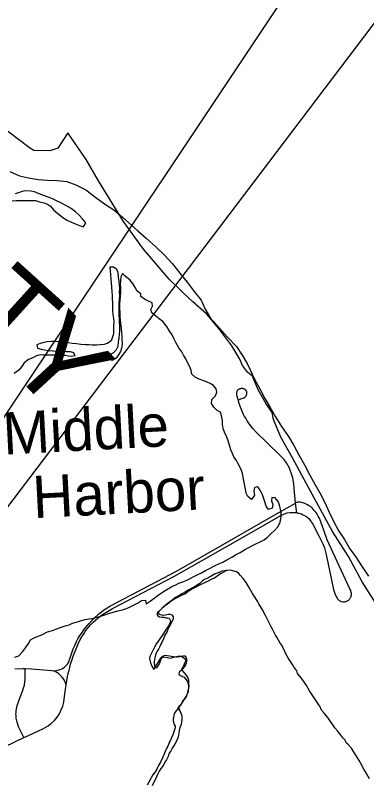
# Model space of a CAD drawing. Extents: x -12 to 34, y 0 to 22.
# Drawn here: x 3.469 to 4.257, y 18.646 to 20.374 of the extents above; entities that cross this region are included whole.
import ezdxf

# ---------------------------------------------------------------- set-up
doc = ezdxf.new("R2010")
doc.units = 0
for name, color, linetype in [('GM_X_Adjacent_County', 7, 'Continuous'), ('GM_X_Airport_Location_Class_2', 7, 'Continuous'), ('GM_X_Major_Lake_Text', 7, 'Continuous'), ('GM_X_Major_River', 7, 'Continuous'), ('GM_X_Minor_Lake', 7, 'Continuous'), ('GM_X_Minor_River', 7, 'Continuous'), ('GM_X_Minor_River_Text', 7, 'Continuous')]:
    doc.layers.add(name, color=color, linetype=linetype)

msp = doc.modelspace()

# ---------------------------------------------------------------- linework, layer by layer
at = {"layer": 'GM_X_Adjacent_County'}
msp.add_lwpolyline([(4.3077, 20.7695), (2.2584, 17.6954), (4.3077, 20.4)], close=True, dxfattribs=at)
at = {"layer": 'GM_X_Airport_Location_Class_2'}
msp.add_lwpolyline([(4.2894, 19.0359), (4.2477, 19.1014), (4.2165, 19.1581), (4.1808, 19.2148), (4.1493, 19.2726), (4.1226, 19.322), (4.0908, 19.38), (4.0645, 19.4267), (4.0481, 19.466), (4.0454, 19.4824), (4.032, 19.5012), (4.0137, 19.5331), (4.0011, 19.5638), (3.9901, 19.5729), (3.9785, 19.5879), (3.9729, 19.6019), (3.9546, 19.6317), (3.9254, 19.6709), (3.899, 19.7032), (3.8673, 19.7311), (3.8453, 19.751), (3.8144, 19.7819), (3.7561, 19.8493), (3.7118, 19.9114), (3.6551, 20.0027), (3.628, 20.0508), (3.5867, 20.1107), (3.5637, 20.0758), (3.5463, 20.0702), (3.5098, 20.0709), (3.5002, 20.0768), (3.4285, 20.1304)], dxfattribs=at)
msp.add_lwpolyline([(4.2894, 19.0359), (4.2477, 19.1014), (4.2165, 19.1581), (4.1808, 19.2148), (4.1493, 19.2726), (4.1226, 19.322), (4.0908, 19.38), (4.0645, 19.4267), (4.0481, 19.466), (4.0454, 19.4824), (4.032, 19.5012), (4.0137, 19.5331), (4.0011, 19.5638), (3.9901, 19.5729), (3.9785, 19.5879), (3.9729, 19.6019), (3.9546, 19.6317), (3.9254, 19.6709), (3.899, 19.7032), (3.8673, 19.7311), (3.8453, 19.751), (3.8144, 19.7819), (3.7561, 19.8493), (3.7118, 19.9114), (3.6551, 20.0027), (3.628, 20.0508), (3.5867, 20.1107), (3.5637, 20.0758), (3.5463, 20.0702), (3.5098, 20.0709), (3.5002, 20.0768), (3.4285, 20.1304)], dxfattribs=at)
at = {"layer": 'GM_X_Major_River'}
msp.add_line((4.1007, 19.2569), (4.098, 19.2786), dxfattribs=at)
for points in [[(3.9703, 19.5105), (3.9711, 19.511), (3.9719, 19.5113), (3.9735, 19.5119), (3.9752, 19.5124), (3.9794, 19.5139), (3.9805, 19.5143), (3.9814, 19.5148), (3.9822, 19.5152), (3.983, 19.5157), (3.984, 19.5164), (3.9847, 19.517), (3.9852, 19.5175), (3.9861, 19.5186), (3.9868, 19.5197), (3.9873, 19.5206), (3.9876, 19.5212), (3.9879, 19.5222), (3.9882, 19.5232), (3.9884, 19.5242), (3.9884, 19.5255), (3.9883, 19.5272), (3.9881, 19.5282), (3.9877, 19.5294), (3.9874, 19.5301), (3.9867, 19.5313), (3.9857, 19.5326), (3.9847, 19.5335), (3.984, 19.534), (3.9833, 19.5344), (3.9821, 19.535), (3.9805, 19.5355), (3.9789, 19.5358), (3.9774, 19.5359), (3.9759, 19.5358), (3.9744, 19.5356), (3.973, 19.5352), (3.9715, 19.5346), (3.9703, 19.5339), (3.9696, 19.5335), (3.969, 19.533), (3.9678, 19.5319), (3.9669, 19.5307), (3.9663, 19.5295), (3.9658, 19.528), (3.9655, 19.5265), (3.9653, 19.525), (3.9654, 19.5231), (3.9655, 19.5213), (3.9661, 19.5192), (3.9685, 19.5115)], [(4.098, 19.2786), (4.0966, 19.2948), (4.0951, 19.3113), (4.0937, 19.3225), (4.0928, 19.3296), (4.0917, 19.335), (4.0905, 19.3399), (4.0882, 19.3466), (4.0834, 19.3581), (4.0774, 19.3689), (4.072, 19.3764), (4.0659, 19.3835), (4.0324, 19.4157), (4.0099, 19.4369), (4.0016, 19.4462), (3.9942, 19.4561), (3.992, 19.4592), (3.9891, 19.4637), (3.9859, 19.4692), (3.9835, 19.4732), (3.9813, 19.4773), (3.9787, 19.4829), (3.974, 19.4944), (3.9706, 19.5045), (3.9699, 19.5069), (3.9696, 19.5079), (3.9696, 19.5086), (3.9697, 19.5093), (3.9703, 19.5105)], [(3.555, 18.9016), (3.5586, 18.9019), (3.5621, 18.9024), (3.564, 18.9028), (3.567, 18.9037), (3.5694, 18.9045), (3.5727, 18.906), (3.5767, 18.9083), (3.5792, 18.9101), (3.5807, 18.9112), (3.5829, 18.9132), (3.5845, 18.915), (3.5858, 18.9167), (3.5871, 18.9187), (3.5883, 18.921), (3.5893, 18.9233), (3.5903, 18.9259), (3.5962, 18.9443), (3.5988, 18.9511), (3.6019, 18.9588), (3.6035, 18.9621), (3.6059, 18.9672), (3.6093, 18.9734), (3.6137, 18.9806), (3.6193, 18.9888), (3.6242, 18.9961), (3.6288, 19.0018), (3.6341, 19.0081), (3.6448, 19.0194), (3.6564, 19.0298), (3.6688, 19.0391), (3.682, 19.0473), (3.8306, 19.1258), (3.8603, 19.1429), (3.9144, 19.1737), (4.0549, 19.254), (4.098, 19.2786)], [(4.2138, 19.0587), (4.2164, 19.0602), (4.218, 19.0614), (4.2192, 19.0627), (4.22, 19.0637), (4.2208, 19.0649), (4.2215, 19.0661), (4.2221, 19.0674), (4.2225, 19.0684), (4.2229, 19.0694), (4.2231, 19.0705), (4.2232, 19.0718), (4.2233, 19.0732), (4.2233, 19.0749), (4.2232, 19.076), (4.2231, 19.0768), (4.2228, 19.0785), (4.2223, 19.0799), (4.2219, 19.081), (4.221, 19.0834), (4.22, 19.0856), (4.2, 19.1279), (4.1691, 19.1957), (4.1625, 19.2131), (4.1576, 19.2279), (4.1564, 19.2321), (4.1548, 19.2367), (4.1531, 19.2406), (4.151, 19.2452), (4.1489, 19.2489), (4.1465, 19.2534), (4.1438, 19.2573), (4.1422, 19.2596), (4.1399, 19.2622), (4.1376, 19.2647), (4.135, 19.2675), (4.1337, 19.2685), (4.1321, 19.2699), (4.1299, 19.2716), (4.1273, 19.2733), (4.1249, 19.2748), (4.1219, 19.2762), (4.119, 19.2774), (4.1168, 19.2783), (4.1143, 19.2791), (4.1119, 19.2798), (4.1089, 19.2804), (4.1075, 19.2806), (4.1062, 19.2806), (4.1054, 19.2806), (4.1041, 19.2805), (4.1029, 19.2804), (4.1017, 19.28), (4.1003, 19.2795), (4.098, 19.2786)], [(3.5827, 18.87), (3.5833, 18.8744), (3.586, 18.889), (3.5866, 18.8921), (3.5873, 18.8957), (3.5892, 18.9033), (3.5907, 18.9094), (3.5928, 18.9168), (3.594, 18.9211), (3.5951, 18.9244), (3.5986, 18.9345), (3.6065, 18.9547), (3.6099, 18.9624), (3.6143, 18.9716), (3.6192, 18.9799), (3.623, 18.9857), (3.6255, 18.9896), (3.6294, 18.9951), (3.6346, 19.0015), (3.6384, 19.0059), (3.6433, 19.011), (3.6483, 19.0155), (3.6536, 19.0199), (3.6589, 19.0242), (3.6619, 19.0263), (3.6681, 19.0306), (3.687, 19.0413), (3.8246, 19.1133), (3.8866, 19.1487), (3.9945, 19.2103), (4.0645, 19.2506), (4.0729, 19.2546), (4.0788, 19.2565), (4.0849, 19.2574), (4.088, 19.2575), (4.0928, 19.2576), (4.0957, 19.2574), (4.0984, 19.2572), (4.1007, 19.2569)], [(4.1007, 19.2569), (4.1023, 19.2567), (4.1042, 19.2562), (4.1063, 19.2557), (4.1091, 19.2549), (4.111, 19.2542), (4.1136, 19.2531), (4.1178, 19.2509), (4.123, 19.2476), (4.1277, 19.2436), (4.1318, 19.2389), (4.1368, 19.231), (4.1512, 19.2035), (4.1593, 19.1868), (4.1627, 19.1781), (4.166, 19.1661), (4.1791, 19.1023), (4.1831, 19.0841), (4.1861, 19.0752), (4.1901, 19.0668), (4.1914, 19.0647), (4.1924, 19.0633), (4.1934, 19.0621), (4.1948, 19.0607), (4.1962, 19.0596), (4.1974, 19.0589), (4.1988, 19.0582), (4.2001, 19.0576), (4.2017, 19.0572), (4.2048, 19.0568), (4.2079, 19.0569), (4.2093, 19.0572), (4.2109, 19.0576), (4.2138, 19.0587)], [(3.4678, 18.9062), (3.4865, 18.907), (3.4903, 18.9069)], [(3.4874, 18.7515), (3.4767, 18.7743), (3.4735, 18.7831), (3.4724, 18.7866), (3.4718, 18.7893), (3.4713, 18.7923), (3.4707, 18.7954), (3.4703, 18.7978), (3.4701, 18.8015), (3.47, 18.8041), (3.4701, 18.8072), (3.4702, 18.8094), (3.4707, 18.8132), (3.471, 18.8154), (3.4719, 18.8201), (3.4729, 18.8233), (3.4741, 18.8272), (3.4755, 18.8321), (3.4853, 18.8578), (3.4871, 18.8633), (3.4879, 18.8659), (3.4889, 18.8695), (3.4895, 18.8724), (3.4899, 18.8748), (3.4901, 18.8778), (3.4903, 18.8811), (3.4905, 18.8845), (3.4903, 18.9069)], [(3.4903, 18.9069), (3.5051, 18.9064), (3.5497, 18.902), (3.555, 18.9016)], [(3.5827, 18.87), (3.5811, 18.8747), (3.5797, 18.8777), (3.5779, 18.881), (3.5743, 18.8864), (3.5722, 18.8885), (3.5676, 18.8934), (3.566, 18.8949), (3.5629, 18.8972), (3.555, 18.9016)], [(3.4874, 18.7515), (3.4978, 18.7565), (3.5317, 18.7721), (3.5425, 18.7782), (3.55, 18.7837), (3.5567, 18.7901), (3.5626, 18.7973), (3.5676, 18.8052), (3.5717, 18.8136), (3.575, 18.8223), (3.5773, 18.8313), (3.5799, 18.8497), (3.5827, 18.87)], [(3.2569, 18.6617), (3.2728, 18.6624), (3.2882, 18.6641), (3.3034, 18.6671), (3.3153, 18.6706), (3.3268, 18.6753), (3.3802, 18.7002), (3.4874, 18.7515)]]:
    msp.add_lwpolyline(points, dxfattribs=at)
at = {"layer": 'GM_X_Minor_Lake'}
for points in [[(3.4617, 19.9576), (3.4704, 19.9584), (3.4814, 19.9584), (3.4928, 19.9588), (3.5034, 19.9585), (3.5137, 19.9582), (3.5228, 19.9556), (3.5327, 19.9529), (3.5407, 19.9503), (3.5479, 19.9458), (3.5544, 19.9378), (3.5643, 19.9291), (3.5746, 19.9208), (3.5845, 19.9144), (3.5944, 19.9095), (3.6051, 19.9054), (3.6127, 19.9024), (3.6214, 19.899), (3.6271, 19.9081), (3.6191, 19.9176), (3.6118, 19.9255), (3.6034, 19.9331), (3.5939, 19.9407), (3.5817, 19.9475), (3.5706, 19.9535), (3.5596, 19.9584), (3.5505, 19.9629), (3.5425, 19.9659), (3.5315, 19.9697), (3.5223, 19.9734), (3.5113, 19.9779), (3.5033, 19.9794), (3.4912, 19.9801), (3.4836, 19.9786), (3.4756, 19.9759), (3.4684, 19.9736)], [(3.7501, 19.749), (3.7425, 19.755), (3.7372, 19.7641), (3.7314, 19.7725), (3.7257, 19.7804), (3.7162, 19.7876), (3.7089, 19.7944), (3.7055, 19.7868), (3.7044, 19.7777), (3.7041, 19.7693), (3.7045, 19.7621), (3.7046, 19.7533), (3.7039, 19.7419), (3.7031, 19.7339), (3.7024, 19.7267), (3.7025, 19.7157), (3.7033, 19.7062), (3.7033, 19.697), (3.7038, 19.6894), (3.7049, 19.6815), (3.7065, 19.6716), (3.7073, 19.6605), (3.7077, 19.6529), (3.7078, 19.645), (3.7082, 19.6377), (3.7079, 19.629), (3.7049, 19.6191), (3.7004, 19.6115), (3.6947, 19.6042), (3.686, 19.5992), (3.6784, 19.6045), (3.6802, 19.6117), (3.6897, 19.6167), (3.6961, 19.624), (3.6995, 19.6312), (3.7006, 19.64), (3.7017, 19.6499), (3.7028, 19.6575), (3.7035, 19.6662), (3.7034, 19.6761), (3.7026, 19.6845), (3.7022, 19.6917), (3.7014, 19.7008), (3.7014, 19.7084), (3.7017, 19.7198), (3.702, 19.7275), (3.7028, 19.7366), (3.7031, 19.7442), (3.7027, 19.7533), (3.703, 19.7609), (3.7022, 19.7681), (3.7014, 19.7769), (3.7006, 19.7868), (3.6994, 19.7963), (3.6963, 19.8035), (3.6887, 19.8084), (3.6811, 19.8084), (3.6812, 19.8004), (3.6823, 19.7916), (3.6828, 19.781), (3.684, 19.773), (3.6848, 19.7646), (3.6856, 19.7532), (3.6864, 19.746), (3.6864, 19.738), (3.6869, 19.7274), (3.6865, 19.7186), (3.6869, 19.711), (3.6874, 19.7023), (3.6893, 19.6932), (3.6897, 19.6859), (3.689, 19.6768), (3.6891, 19.6673), (3.6887, 19.6589), (3.6861, 19.6502), (3.6839, 19.6429), (3.6756, 19.6368), (3.6676, 19.6345), (3.6592, 19.6341), (3.6516, 19.6337), (3.6414, 19.6336), (3.6334, 19.634), (3.6262, 19.6339), (3.6156, 19.635), (3.6057, 19.6361), (3.5962, 19.6372)], [(3.7112, 19.7868), (3.7113, 19.7868)], [(3.9434, 19.1513), (3.9544, 19.1571), (3.9631, 19.1624), (3.9737, 19.1674), (3.9855, 19.1751), (3.9942, 19.1797), (4.0014, 19.1832), (4.0089, 19.1866), (4.0184, 19.1916), (4.0271, 19.1958), (4.0358, 19.2027), (4.0434, 19.21), (4.0509, 19.2168), (4.0585, 19.226), (4.063, 19.2355), (4.0645, 19.2428), (4.0652, 19.25), (4.0652, 19.2572), (4.064, 19.2652), (4.0617, 19.2736), (4.059, 19.2823), (4.0521, 19.2902), (4.0445, 19.2913), (4.0438, 19.2837), (4.0468, 19.275), (4.0457, 19.267), (4.037, 19.2639), (4.0321, 19.2715), (4.029, 19.281), (4.0263, 19.2882), (4.0236, 19.2973), (4.0186, 19.3076), (4.0132, 19.3148), (4.006, 19.3132), (4.0042, 19.3052), (4.0057, 19.2965), (3.9989, 19.2866), (3.9906, 19.2934), (3.9871, 19.301), (3.9855, 19.3097), (3.9836, 19.3169), (3.982, 19.3287), (3.9805, 19.3367), (3.9785, 19.345), (3.9754, 19.3541), (3.9693, 19.3667), (3.9651, 19.3739), (3.9593, 19.3822), (3.9563, 19.3898), (3.9528, 19.3985), (3.9493, 19.4084), (3.9466, 19.4187), (3.9432, 19.427), (3.9386, 19.438), (3.9355, 19.4464), (3.9339, 19.4551), (3.9335, 19.4631), (3.9323, 19.4715), (3.9292, 19.4828), (3.9216, 19.4862), (3.914, 19.4938), (3.9094, 19.5021), (3.9097, 19.5113), (3.9184, 19.5197), (3.9214, 19.5277), (3.9194, 19.5353), (3.9133, 19.5425), (3.9061, 19.5474), (3.8981, 19.5508), (3.8897, 19.5538), (3.8817, 19.5568), (3.8722, 19.5613), (3.8646, 19.5685), (3.8634, 19.5761), (3.8607, 19.5844), (3.8554, 19.5947), (3.8511, 19.6023), (3.8462, 19.611), (3.8423, 19.6182), (3.8354, 19.6277), (3.8289, 19.6394), (3.8243, 19.6485), (3.8209, 19.6569), (3.8144, 19.666), (3.8086, 19.6751), (3.7998, 19.6865), (3.7914, 19.6929), (3.7842, 19.6986), (3.775, 19.7061), (3.7731, 19.7137), (3.7765, 19.7213), (3.7757, 19.7286), (3.7677, 19.7323), (3.7589, 19.7365), (3.7502, 19.7429), (3.7501, 19.749)], [(3.5962, 19.6372), (3.5878, 19.6383), (3.578, 19.639), (3.5669, 19.6405), (3.5582, 19.6416), (3.5499, 19.6419), (3.5404, 19.6411), (3.5328, 19.6396), (3.5241, 19.6373), (3.5165, 19.6338), (3.5184, 19.6266), (3.5268, 19.6247), (3.5344, 19.6232), (3.542, 19.6217), (3.5526, 19.6203), (3.5629, 19.6199), (3.5739, 19.6196), (3.5826, 19.6193), (3.5917, 19.6189), (3.5993, 19.6167), (3.6024, 19.6091), (3.5952, 19.6079), (3.588, 19.609), (3.5808, 19.6098), (3.5736, 19.6101), (3.5663, 19.6108), (3.5572, 19.6112), (3.5496, 19.6108), (3.539, 19.6107), (3.5318, 19.6107), (3.5246, 19.6114), (3.5162, 19.6095), (3.5075, 19.6052), (3.498, 19.6014), (3.4886, 19.5934), (3.4829, 19.5857), (3.4762, 19.5769), (3.4663, 19.5697)], [(3.4673, 18.932), (3.4768, 18.9355), (3.4847, 18.9442), (3.4915, 18.9534), (3.4979, 18.9626), (3.5028, 18.9713), (3.5111, 18.9759), (3.5199, 18.9798), (3.5278, 18.9828), (3.5411, 18.989), (3.5521, 18.9921), (3.5615, 18.9963), (3.5718, 18.9994), (3.5805, 19.0025), (3.5892, 19.0048), (3.5968, 19.0083), (3.6101, 19.0121), (3.6173, 19.0148), (3.6252, 19.0168), (3.6347, 19.0183), (3.6419, 19.0195), (3.6491, 19.0211), (3.6578, 19.0234), (3.6692, 19.0272), (3.6775, 19.0307), (3.6912, 19.0342), (3.6991, 19.0361), (3.709, 19.0388), (3.7162, 19.0408), (3.7238, 19.0435), (3.7427, 19.0534), (3.7518, 19.0596), (3.7609, 19.06), (3.7621, 19.052), (3.7716, 19.0581), (3.7806, 19.065), (3.7897, 19.0719), (3.7969, 19.0765), (3.8048, 19.0822), (3.8124, 19.0868), (3.82, 19.0907), (3.8287, 19.0949), (3.8359, 19.0987), (3.8446, 19.1018), (3.8522, 19.1049), (3.8598, 19.1083), (3.8692, 19.1137), (3.8772, 19.1172), (3.8863, 19.1214), (3.8957, 19.1271), (3.9029, 19.131), (3.9177, 19.1379), (3.9268, 19.1425), (3.9344, 19.146), (3.9434, 19.1513)], [(3.9439, 19.1277), (3.9394, 19.1251), (3.9307, 19.1201), (3.9269, 19.1178), (3.922, 19.1143), (3.9156, 19.1101), (3.911, 19.1082), (3.9016, 19.1028), (3.8962, 19.1009), (3.8887, 19.0971), (3.8853, 19.0955), (3.8739, 19.0898), (3.8667, 19.0856), (3.8588, 19.081), (3.8489, 19.0741), (3.8451, 19.0725), (3.8395, 19.0698), (3.8326, 19.066), (3.8285, 19.0641), (3.8243, 19.0618), (3.8175, 19.0572), (3.8141, 19.0545), (3.8092, 19.0503), (3.8046, 19.0476), (3.8012, 19.0446), (3.7975, 19.0419), (3.7941, 19.0381), (3.791, 19.0346), (3.7892, 19.0308), (3.7926, 19.0286), (3.796, 19.0271), (3.8006, 19.0263), (3.8059, 19.0275), (3.812, 19.0287), (3.8165, 19.0291), (3.8203, 19.0272), (3.823, 19.0226), (3.823, 19.0181), (3.8211, 19.0135), (3.8174, 19.0055), (3.8132, 18.999), (3.8106, 18.9929), (3.8087, 18.9887), (3.8046, 18.9815), (3.8012, 18.9738), (3.7978, 18.9655), (3.7956, 18.9617), (3.793, 18.9563), (3.7903, 18.9506), (3.7873, 18.946), (3.7851, 18.9415), (3.7836, 18.9373), (3.7828, 18.9338), (3.7813, 18.9278), (3.7806, 18.9217), (3.7806, 18.9179), (3.7814, 18.9129), (3.7826, 18.9091), (3.786, 18.908), (3.7886, 18.9118), (3.792, 18.9175), (3.7939, 18.9217), (3.7954, 18.9259), (3.7965, 18.9297), (3.8003, 18.9332), (3.8098, 18.9313), (3.8132, 18.9306), (3.8166, 18.9302), (3.8216, 18.9317), (3.8269, 18.9333), (3.8333, 18.9345), (3.8367, 18.9349), (3.8413, 18.9345), (3.8474, 18.93), (3.8508, 18.9277), (3.8505, 18.9231), (3.8486, 18.9189), (3.8467, 18.914), (3.8448, 18.9098), (3.8418, 18.9056), (3.843, 18.9022), (3.8468, 18.898), (3.8506, 18.8935), (3.854, 18.8893), (3.856, 18.8855), (3.8575, 18.8813), (3.8575, 18.8756), (3.8576, 18.8722), (3.858, 18.8669), (3.8576, 18.8616), (3.8561, 18.8566), (3.8542, 18.8501), (3.8528, 18.8456), (3.8509, 18.8418), (3.8482, 18.8372), (3.8448, 18.8338), (3.8414, 18.8292), (3.8399, 18.8257), (3.8366, 18.8219), (3.8335, 18.8181), (3.8381, 18.8117)], [(4.2641, 18.6585), (4.2553, 18.6748), (4.2515, 18.6805), (4.2438, 18.6949), (4.2404, 18.6998), (4.2335, 18.7124), (4.2304, 18.7169), (4.2232, 18.7275), (4.2151, 18.737), (4.2113, 18.74), (4.2094, 18.7461), (4.2044, 18.751), (4.1976, 18.7597), (4.1918, 18.7665), (4.1861, 18.7737), (4.1804, 18.7821), (4.1762, 18.7874), (4.1704, 18.7965), (4.1624, 18.8063), (4.1563, 18.8135), (4.1521, 18.8219), (4.1498, 18.8253), (4.1444, 18.834), (4.1367, 18.8457), (4.1295, 18.8564), (4.1226, 18.8689), (4.1191, 18.873), (4.1115, 18.8852), (4.1019, 18.8958), (4.1004, 18.9015), (4.0943, 18.9102), (4.0912, 18.9159), (4.082, 18.9295), (4.0763, 18.9401), (4.0736, 18.9451), (4.0667, 18.9591), (4.0632, 18.964), (4.0556, 18.9769), (4.0525, 18.9815), (4.046, 18.9951), (4.0429, 19.0004), (4.0372, 19.0126), (4.0345, 19.0168), (4.0303, 19.0259), (4.0238, 19.0384), (4.0211, 19.0422), (4.0157, 19.0524), (4.013, 19.0566), (4.0073, 19.0661), (4.0015, 19.0752), (3.9924, 19.0911), (3.987, 19.1002), (3.9805, 19.1089), (3.974, 19.1161), (3.9702, 19.1206), (3.9652, 19.124), (3.9572, 19.1259), (3.9519, 19.1274), (3.939, 19.1266), (3.9326, 19.1254), (3.9261, 19.1227), (3.917, 19.1193), (3.9098, 19.115), (3.9011, 19.1101), (3.8932, 19.107), (3.889, 19.1035), (3.8826, 19.0978), (3.8735, 19.0921), (3.8648, 19.0875), (3.8569, 19.0825), (3.8485, 19.0779), (3.8428, 19.0744), (3.8383, 19.0717), (3.8281, 19.066), (3.8209, 19.0603), (3.8152, 19.0564), (3.8118, 19.0534), (3.8054, 19.048), (3.8016, 19.0453), (3.7963, 19.04), (3.7914, 19.0358), (3.7876, 19.0327), (3.7861, 19.0289), (3.7884, 19.0255), (3.7926, 19.0229), (3.7972, 19.0225), (3.8021, 19.0218), (3.8059, 19.021), (3.8105, 19.0207), (3.8139, 19.0199), (3.8166, 19.0157), (3.8173, 19.0123), (3.8159, 19.0085), (3.8144, 19.0051), (3.8113, 19.0001), (3.8061, 18.9929)], [(3.8061, 18.9929), (3.8015, 18.9856), (3.7966, 18.9788), (3.7932, 18.9738), (3.7891, 18.9681), (3.7857, 18.9628), (3.7812, 18.9551), (3.7771, 18.9475), (3.7725, 18.9384), (3.7707, 18.9338), (3.7699, 18.9292), (3.7703, 18.9254), (3.7719, 18.9193), (3.7757, 18.9106), (3.7796, 18.9049), (3.7833, 18.9103), (3.7852, 18.9137), (3.7878, 18.9183), (3.7905, 18.9225), (3.7942, 18.9293), (3.7984, 18.9339), (3.8026, 18.9362), (3.806, 18.9366), (3.8098, 18.9359), (3.8151, 18.9355), (3.8196, 18.9348), (3.8238, 18.9337), (3.828, 18.9329), (3.8318, 18.9329), (3.8383, 18.9341), (3.8417, 18.9345), (3.8458, 18.9353), (3.8493, 18.9349), (3.8519, 18.9307), (3.8527, 18.9269), (3.8531, 18.9231), (3.8524, 18.919), (3.8505, 18.9148), (3.8486, 18.9113), (3.8448, 18.9071), (3.8414, 18.9033), (3.8365, 18.8987), (3.8354, 18.8942), (3.8392, 18.8911), (3.8438, 18.8885), (3.848, 18.887), (3.853, 18.8809), (3.8553, 18.8771), (3.8564, 18.8722), (3.8572, 18.8646), (3.8565, 18.8562), (3.8558, 18.8521), (3.8539, 18.8475), (3.8501, 18.8414), (3.846, 18.8353), (3.8437, 18.8318), (3.8392, 18.8246), (3.8354, 18.8196), (3.8328, 18.8154), (3.8298, 18.812), (3.8267, 18.8082), (3.8249, 18.8044), (3.823, 18.7937), (3.823, 18.7895), (3.825, 18.7812), (3.8277, 18.7774), (3.8273, 18.7736), (3.8254, 18.7664), (3.8221, 18.7576), (3.8168, 18.7458), (3.8149, 18.742), (3.8108, 18.7325), (3.8089, 18.7287), (3.8052, 18.7203), (3.8033, 18.7168), (3.7995, 18.7077), (3.7943, 18.6966), (3.7898, 18.689), (3.7875, 18.6844), (3.786, 18.6806), (3.7826, 18.6749), (3.7777, 18.6681), (3.7736, 18.6612), (3.7683, 18.6513), (3.7646, 18.6444)], [(3.8061, 18.9929), (3.8015, 18.9856), (3.7966, 18.9788), (3.7932, 18.9738), (3.7891, 18.9681), (3.7857, 18.9628), (3.7812, 18.9551), (3.7771, 18.9475), (3.7725, 18.9384), (3.7707, 18.9338), (3.7699, 18.9292), (3.7703, 18.9254), (3.7719, 18.9193), (3.7757, 18.9106), (3.7796, 18.9049), (3.7833, 18.9103), (3.7852, 18.9137), (3.7878, 18.9183), (3.7905, 18.9225), (3.7942, 18.9293), (3.7984, 18.9339), (3.8026, 18.9362), (3.806, 18.9366), (3.8098, 18.9359), (3.8151, 18.9355), (3.8196, 18.9348), (3.8238, 18.9337), (3.828, 18.9329), (3.8318, 18.9329), (3.8383, 18.9341), (3.8417, 18.9345), (3.8458, 18.9353), (3.8493, 18.9349), (3.8519, 18.9307), (3.8527, 18.9269), (3.8531, 18.9231), (3.8524, 18.919), (3.8505, 18.9148), (3.8486, 18.9113), (3.8448, 18.9071), (3.8414, 18.9033), (3.8365, 18.8987), (3.8354, 18.8942), (3.8392, 18.8911), (3.8438, 18.8885), (3.848, 18.887), (3.853, 18.8809), (3.8553, 18.8771), (3.8564, 18.8722), (3.8572, 18.8646), (3.8565, 18.8562), (3.8558, 18.8521), (3.8539, 18.8475), (3.8501, 18.8414), (3.846, 18.8353), (3.8437, 18.8318), (3.8392, 18.8246), (3.835, 18.8191)], [(3.835, 18.8191), (3.8424, 18.8014), (3.8427, 18.7976), (3.8424, 18.7919), (3.8409, 18.7813), (3.8379, 18.7744), (3.8368, 18.7676), (3.8361, 18.7619), (3.8342, 18.7531), (3.8312, 18.7451), (3.8267, 18.7371), (3.8207, 18.7279), (3.8177, 18.7218), (3.8143, 18.7169), (3.8121, 18.7093), (3.8083, 18.7017), (3.8057, 18.6982), (3.8015, 18.6902), (3.7993, 18.6868), (3.7955, 18.6822), (3.7917, 18.6761), (3.788, 18.6685), (3.7846, 18.6609), (3.7801, 18.6529), (3.776, 18.6433)], [(3.8381, 18.8117), (3.8424, 18.8014), (3.8427, 18.7976), (3.8424, 18.7919), (3.8409, 18.7813), (3.8379, 18.7744), (3.8368, 18.7676), (3.8361, 18.7619), (3.8342, 18.7531), (3.8312, 18.7451), (3.8267, 18.7371), (3.8207, 18.7279), (3.8177, 18.7218), (3.8143, 18.7169), (3.8121, 18.7093), (3.8083, 18.7017), (3.8057, 18.6982), (3.8015, 18.6902), (3.7993, 18.6868), (3.7955, 18.6822), (3.7917, 18.6761), (3.788, 18.6685), (3.7846, 18.6609), (3.7801, 18.6529), (3.776, 18.6433)]]:
    msp.add_lwpolyline(points, dxfattribs=at)
at = {"layer": 'GM_X_Minor_River'}
msp.add_lwpolyline([(3.4563, 20.0236), (3.4779, 20.0137), (3.498, 20.0091), (3.5201, 20.0057), (3.5406, 20.0042), (3.5626, 20.0031), (3.5842, 20.0012), (3.6043, 19.9939), (3.6271, 19.9825), (3.6495, 19.9651), (3.6688, 19.951), (3.6897, 19.9373), (3.7095, 19.921), (3.7436, 19.8906), (3.7626, 19.8739), (3.7842, 19.8545), (3.8032, 19.8355), (3.8218, 19.8165), (3.8381, 19.7952), (3.8541, 19.7751), (3.8704, 19.7542), (3.886, 19.7344), (3.8951, 19.7146), (3.9072, 19.6937), (3.9266, 19.6724), (3.944, 19.6523), (3.9649, 19.6303), (3.9782, 19.6109), (3.9892, 19.5919), (4.0063, 19.5554), (4.0173, 19.5349), (4.0287, 19.5132), (4.0412, 19.4931), (4.053, 19.4722), (4.0663, 19.4505), (4.0818, 19.4281), (4.094, 19.4076), (4.1058, 19.3851), (4.1179, 19.3646), (4.1301, 19.3411), (4.1414, 19.3209), (4.1525, 19.3012), (4.1631, 19.2814), (4.173, 19.2582), (4.184, 19.2362), (4.1954, 19.2157), (4.2079, 19.1963), (4.22, 19.1758), (4.2337, 19.1564), (4.2477, 19.1355), (4.2614, 19.1146)], dxfattribs=at)

# ---------------------------------------------------------------- texts
at = {"layer": 'GM_X_Major_Lake_Text'}
for s, rotation, p in [('T', 317.8931, (3.3425, 19.6855)), ('Y', 312.5742, (3.4443, 19.5938))]:
    msp.add_text(s, height=0.1894, rotation=rotation, dxfattribs=at).set_placement(p)
at = {"layer": 'GM_X_Minor_River_Text'}
for s, rotation, p in [('Middle', 3.0086, (3.4427, 19.3872)), ('Harbor', 3.0081, (3.5097, 19.2444))]:
    msp.add_text(s, height=0.09476, rotation=rotation, dxfattribs=at).set_placement(p)

doc.saveas('drawing.dxf')
